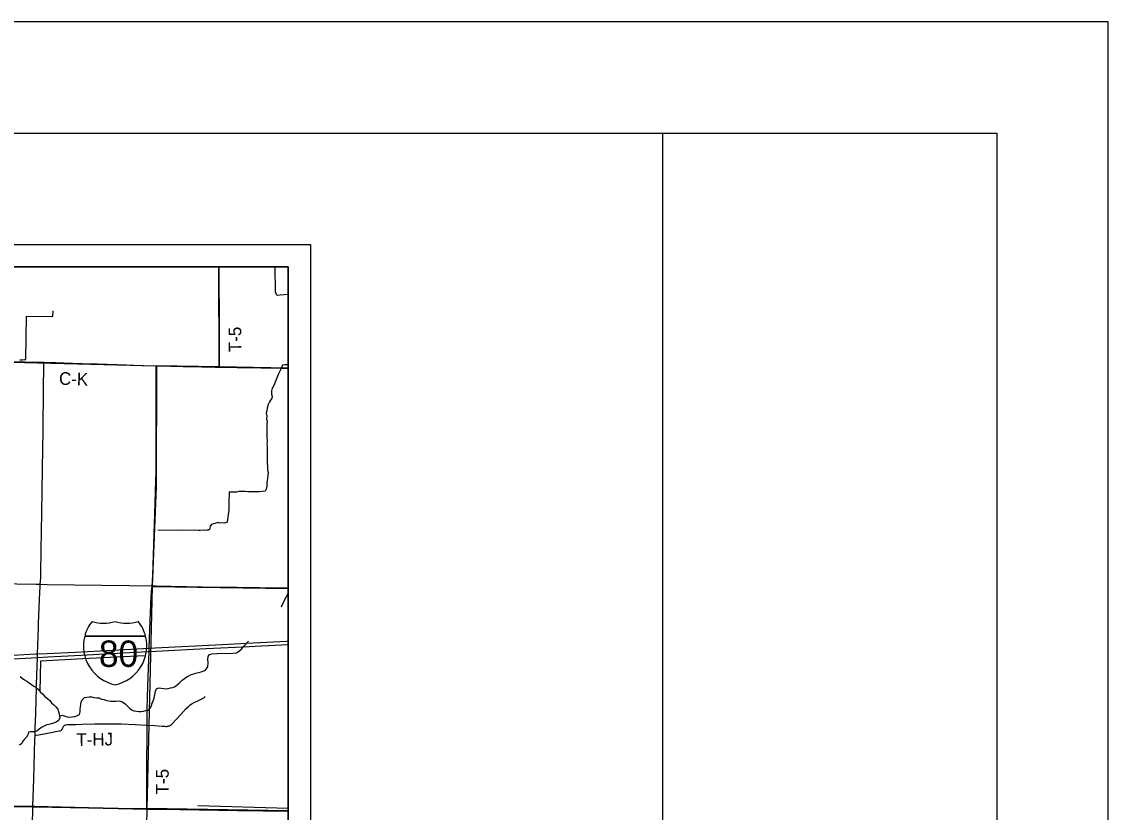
# Model space of a CAD drawing. Extents: x -21.7 to 34, y 0 to 22.
# Drawn here: x 29.12 to 34, y 18.453 to 22 of the extents above; entities that cross this region are included whole.
import ezdxf

# ---------------------------------------------------------------- set-up
doc = ezdxf.new("R2010")
doc.units = 0
for name, color, linetype in [('Default', 7, 'Continuous'), ('GM_X_County_Road', 7, 'Continuous'), ('GM_X_County_Road_Text', 7, 'Continuous'), ('GM_X_Interchange_Ramps', 7, 'Continuous'), ('GM_X_Interstate_Location', 7, 'Continuous'), ('GM_X_Interstate_Route', 7, 'Continuous'), ('GM_X_Interstate_Shield', 7, 'Continuous'), ('GM_X_Minor_River', 7, 'Continuous'), ('GM_X_Township_Road', 7, 'Continuous'), ('GM_X_Township_Road_Text', 7, 'Continuous'), ('SH_Border', 7, 'Continuous'), ('SH_Cut_Line', 7, 'Continuous'), ('SH_Data', 7, 'Continuous')]:
    doc.layers.add(name, color=color, linetype=linetype)

msp = doc.modelspace()

# ---------------------------------------------------------------- linework, layer by layer
at = {"layer": 'Default'}
for points in [[(30.006, 20.9), (29.0167, 20.9), (29.0129, 20.4744), (29.7259, 20.4559), (30.0077, 20.4514)], [(30.3167, 20.4464), (30.3167, 20.9), (30.006, 20.9), (30.0077, 20.4514)], [(30.3167, 19.4571), (30.3167, 20.4464), (30.0077, 20.4514), (29.7259, 20.4559), (29.7237, 19.914), (29.706, 19.4656)], [(30.3167, 18.4589), (30.3167, 19.4571), (29.706, 19.4656), (29.6819, 18.4704)], [(30.3167, 17.4474), (30.3167, 18.4589), (29.6819, 18.4704), (29.6632, 17.4593)]]:
    msp.add_lwpolyline(points, close=True, dxfattribs=at)
at = {"layer": 'GM_X_County_Road'}
for points in [[(29.0187, 20.4775), (29.0655, 20.4763), (29.2054, 20.4724), (29.2205, 20.472)], [(29.2037, 19.4762), (29.2057, 19.5049), (29.2066, 19.5267), (29.2084, 19.6294), (29.2108, 19.7973), (29.2122, 19.8938), (29.2152, 20.0866), (29.2164, 20.1581), (29.2164, 20.1706), (29.2166, 20.2017), (29.2173, 20.2421), (29.2179, 20.2763), (29.2186, 20.3447), (29.2203, 20.4629), (29.2205, 20.472)], [(29.2205, 20.472), (29.2738, 20.4705), (29.3483, 20.4681), (29.3918, 20.4667), (29.4602, 20.4648), (29.5908, 20.4605), (29.6591, 20.4581), (29.7244, 20.4565)], [(29.7244, 20.4565), (29.7897, 20.4549), (29.8456, 20.4539), (29.8736, 20.4531), (29.9296, 20.4519), (29.9886, 20.4505), (30.0091, 20.4503)], [(30.0091, 20.4503), (30.0881, 20.4492), (30.1938, 20.4479), (30.2902, 20.4464), (30.3167, 20.4461)], [(28.5268, 19.4873), (28.5787, 19.4865), (28.7466, 19.4836), (28.8305, 19.4824), (28.874, 19.4815), (28.9611, 19.4803), (29.0108, 19.4795), (29.1849, 19.4765), (29.2037, 19.4762)], [(29.1805, 18.7981), (29.1813, 18.8288), (29.183, 18.8628), (29.1837, 18.8942), (29.1842, 18.9147), (29.1848, 18.9395), (29.1875, 19.0266), (29.191, 19.148), (29.1911, 19.1508), (29.1915, 19.1634), (29.1953, 19.2813), (29.1963, 19.2999), (29.1996, 19.4088), (29.2011, 19.4398), (29.2029, 19.4646), (29.2037, 19.4762)], [(29.2037, 19.4762), (29.2345, 19.4757), (29.3557, 19.4738), (29.6044, 19.4699), (29.7055, 19.4687)], [(29.7055, 19.4687), (29.7225, 19.4685), (29.9992, 19.4638), (30.0396, 19.4631), (30.0862, 19.4625), (30.1888, 19.4609), (30.2572, 19.4601), (30.3167, 19.4599)], [(29.1704, 18.4779), (29.1705, 18.4805), (29.1742, 18.6015), (29.1797, 18.7815), (29.1805, 18.7981)], [(28.1596, 18.4872), (28.2546, 18.4861), (28.5561, 18.4831), (28.6742, 18.4819), (28.8328, 18.4806), (29.0193, 18.4793), (29.1704, 18.4779)], [(29.1578, 17.5101), (29.1581, 17.535), (29.1585, 17.5645), (29.1595, 17.6359), (29.1616, 17.7788), (29.1626, 17.8564), (29.1637, 17.9433), (29.1649, 18.0241), (29.1659, 18.1172), (29.166, 18.1358), (29.1666, 18.1824), (29.167, 18.229), (29.168, 18.3035), (29.1704, 18.4779)], [(29.1704, 18.4779), (29.1778, 18.4778), (29.4202, 18.4727), (29.6191, 18.4685), (29.6815, 18.4674)], [(29.6815, 18.4674), (29.7434, 18.4663), (30.0916, 18.4614), (30.3167, 18.4584)]]:
    msp.add_lwpolyline(points, dxfattribs=at)
at = {"layer": 'GM_X_Interchange_Ramps'}
for points in [[(29.019, 18.4799), (29.1702, 18.4785), (29.1776, 18.4784), (29.42, 18.4733), (29.6189, 18.4691), (29.6813, 18.468), (29.7432, 18.4669), (30.0914, 18.462), (30.3167, 18.4589), (30.3167, 20.9), (27.8768, 20.9)], [(27.5987, 14.1), (30.3167, 14.1), (30.3167, 18.4589), (30.0914, 18.462), (29.7432, 18.4669), (29.6813, 18.468), (29.6189, 18.4691), (29.42, 18.4733), (29.1776, 18.4784), (29.1702, 18.4785), (29.019, 18.4799)]]:
    msp.add_lwpolyline(points, dxfattribs=at)
at = {"layer": 'GM_X_Interstate_Route'}
for points in [[(29.0829, 19.1422), (29.191, 19.148), (29.2382, 19.1505), (29.3872, 19.1585), (29.5207, 19.1651), (29.6883, 19.1739), (29.6924, 19.1741), (29.7223, 19.1754), (29.949, 19.1873), (30.1136, 19.1954), (30.1974, 19.1999), (30.3167, 19.2058)], [(29.0862, 19.1585), (29.1297, 19.1605), (29.1856, 19.1632), (29.1915, 19.1634), (29.2353, 19.1655), (29.3626, 19.1719), (29.639, 19.1862), (29.693, 19.1891), (29.7197, 19.1905), (30.0209, 19.2062), (30.1296, 19.2121), (30.3097, 19.2213), (30.3167, 19.2216)]]:
    msp.add_lwpolyline(points, dxfattribs=at)
at = {"layer": 'GM_X_Interstate_Shield'}
for p, q in [((29.4033, 19.2429), (29.6765, 19.2429)), ((29.6765, 19.2429), (29.4033, 19.2429)), ((29.6765, 19.2429), (29.4033, 19.2429))]:
    msp.add_line(p, q, dxfattribs=at)
for centre, start, end in [((29.5754, 19.1994), 141.669, 165.8066), ((29.488, 19.4793), 253.0091, 286.9909), ((29.5918, 19.4793), 253.0091, 286.9909), ((29.5044, 19.1994), 14.1934, 38.331), ((29.5754, 19.1994), 165.8066, 258.463), ((29.5044, 19.1994), 281.537, 14.1934)]:
    msp.add_arc(centre, 0.1776, start, end, dxfattribs=at)
at = {"layer": 'GM_X_Minor_River'}
msp.add_line((30.3167, 18.4705), (29.911, 18.4812), dxfattribs=at)
for points in [[(30.2571, 20.9), (30.2581, 20.7874), (30.2622, 20.7828), (30.2635, 20.7763), (30.2688, 20.7732), (30.2817, 20.7741), (30.3167, 20.777)], [(29.1396, 20.4842), (29.1417, 20.6786), (29.2595, 20.6781), (29.2615, 20.7031)], [(29.1119, 20.4829), (29.1229, 20.4838), (29.1324, 20.4843)], [(29.1324, 20.4843), (29.1396, 20.4842)], [(30.3167, 20.4611), (30.303, 20.4607), (30.2908, 20.4587), (30.2856, 20.4444), (30.28, 20.4316), (30.2741, 20.4203), (30.2522, 20.3676), (30.2444, 20.356), (30.2419, 20.3446), (30.242, 20.3287), (30.2455, 20.318), (30.2431, 20.3104), (30.238, 20.3018), (30.2326, 20.294), (30.227, 20.2831), (30.2225, 20.2661), (30.2212, 20.2547), (30.2187, 20.2437), (30.221, 20.23), (30.22, 20.2171), (30.2228, 20.2057), (30.2207, 20.1932), (30.2218, 20.1734), (30.2207, 20.156), (30.2217, 20.1491), (30.221, 20.1366), (30.2222, 20.1184), (30.2219, 20.1062), (30.2221, 20.0967), (30.2222, 20.0618), (30.2223, 20.0303), (30.2228, 20.0196), (30.2245, 20.0067), (30.2241, 19.9904), (30.2269, 19.9766), (30.2238, 19.9535), (30.221, 19.9289), (30.2211, 19.9164), (30.2178, 19.9028), (30.2131, 19.8934), (30.2002, 19.8925), (30.1876, 19.8905), (30.1354, 19.8904), (30.1259, 19.8917), (30.1104, 19.8928), (30.096, 19.8919), (30.0853, 19.8899), (30.0516, 19.889), (30.0506, 19.842), (30.0511, 19.8294), (30.0509, 19.818), (30.0503, 19.8082), (30.0424, 19.754), (30.0325, 19.7504), (30.0231, 19.7518), (30.0098, 19.7498), (30.0015, 19.7533), (29.9878, 19.7483), (29.9802, 19.7473), (29.9725, 19.7437), (29.9674, 19.7369), (29.965, 19.7283), (29.9634, 19.7218), (29.9599, 19.7189), (29.9538, 19.7182), (29.9462, 19.718), (29.9356, 19.7182), (29.922, 19.7174), (29.914, 19.7179), (29.8978, 19.719), (29.8326, 19.7176), (29.7322, 19.7189)], [(29.9577, 19.1243), (29.9569, 19.1395), (29.9571, 19.152), (29.9641, 19.1614), (29.9748, 19.1642), (29.9979, 19.1652), (30.0684, 19.1665), (30.0847, 19.1681), (30.094, 19.1739), (30.1067, 19.1851), (30.1183, 19.1989), (30.1386, 19.2207)], [(29.2027, 18.9937), (29.2058, 19.1326), (29.3951, 19.1428), (29.6697, 19.1559)], [(29.2906, 18.8845), (29.3039, 18.888), (29.3141, 18.8836), (29.3246, 18.8811), (29.3352, 18.8794), (29.3466, 18.8811), (29.3588, 18.8827), (29.371, 18.8866), (29.3806, 18.8921), (29.3823, 18.9039), (29.3825, 18.9149), (29.3839, 18.9259), (29.3856, 18.9372), (29.3877, 18.9471), (29.3921, 18.958), (29.4022, 18.9684), (29.4128, 18.9697), (29.4238, 18.971), (29.4348, 18.9704), (29.445, 18.9687), (29.4582, 18.9665), (29.4681, 18.9663), (29.4793, 18.9612), (29.4906, 18.959), (29.5011, 18.9539), (29.5114, 18.9537), (29.5212, 18.9516), (29.5318, 18.9514), (29.5428, 18.9519), (29.5534, 18.9528), (29.564, 18.9511), (29.5749, 18.9475), (29.585, 18.94), (29.595, 18.9296), (29.6047, 18.9207), (29.6144, 18.9133), (29.6245, 18.9081), (29.6456, 18.9054), (29.6574, 18.9059), (29.668, 18.9069), (29.6775, 18.9093), (29.689, 18.9118), (29.6983, 18.9214), (29.7038, 18.9323), (29.7066, 18.9425), (29.711, 18.9531), (29.7147, 18.9644), (29.7172, 18.9761), (29.72, 18.9867), (29.7217, 18.9965), (29.7254, 19.0063), (29.7357, 19.0107), (29.7463, 19.0101), (29.758, 19.0079), (29.7686, 19.0074), (29.7781, 19.0087), (29.788, 19.0108), (29.7986, 19.0136), (29.8089, 19.0179), (29.8201, 19.0264), (29.8309, 19.0353), (29.8413, 19.0458), (29.8509, 19.0532), (29.8613, 19.0602), (29.8716, 19.0653), (29.882, 19.0711), (29.8927, 19.074), (29.9022, 19.0772), (29.9144, 19.0804), (29.9258, 19.0835), (29.9357, 19.0864), (29.9454, 19.0903), (29.956, 19.1058), (29.9577, 19.1243)], [(29.1127, 19.0623), (29.1225, 19.0553), (29.1333, 19.0479), (29.1438, 19.042), (29.1542, 19.0342), (29.1751, 19.0193), (29.1852, 19.0126), (29.1953, 19.0033), (29.2027, 18.9937), (29.2146, 18.9824), (29.2246, 18.9731), (29.2365, 18.9634), (29.2462, 18.9541), (29.2539, 18.9444), (29.2644, 18.9355), (29.2729, 18.9254), (29.2825, 18.915), (29.2861, 18.9051), (29.2882, 18.8948), (29.2906, 18.8845), (29.2919, 18.8746), (29.286, 18.8644), (29.2749, 18.8571), (29.2631, 18.8527), (29.2535, 18.8495), (29.2429, 18.8475), (29.233, 18.8454), (29.2215, 18.8388), (29.2096, 18.8329), (29.1993, 18.8263), (29.1896, 18.8178), (29.1793, 18.8142), (29.1695, 18.8136), (29.1596, 18.8146), (29.1501, 18.8125), (29.1476, 18.8011), (29.1421, 18.7906), (29.1325, 18.7817), (29.1258, 18.772), (29.1211, 18.7618), (29.1107, 18.7548)]]:
    msp.add_lwpolyline(points, dxfattribs=at)
at = {"layer": 'GM_X_Township_Road'}
for points in [[(30.0091, 20.4503), (30.0091, 20.4567), (30.0092, 20.4722), (30.0089, 20.5374), (30.0082, 20.6151), (30.0065, 20.9)], [(29.7055, 19.4687), (29.7074, 19.4904), (29.7088, 19.5152), (29.7151, 19.7015), (29.7177, 19.7915), (29.7227, 19.9405), (29.7235, 19.9778), (29.7237, 20.0461), (29.7239, 20.2015), (29.7241, 20.2978), (29.7244, 20.4469), (29.7244, 20.4565)], [(29.7244, 20.4565), (29.7897, 20.4549), (29.8456, 20.4539), (29.8736, 20.4531), (29.9296, 20.4519), (29.9886, 20.4505), (30.0091, 20.4503)], [(28.5268, 19.4873), (28.5787, 19.4865), (28.7466, 19.4836), (28.8305, 19.4824), (28.874, 19.4815), (28.9611, 19.4803), (29.0108, 19.4795), (29.1849, 19.4765), (29.2037, 19.4762)], [(29.2037, 19.4762), (29.2345, 19.4757), (29.3557, 19.4738), (29.6044, 19.4699), (29.7055, 19.4687)], [(29.6842, 18.8442), (29.6844, 18.9193), (29.685, 18.966), (29.6866, 19.0188), (29.6896, 19.0995), (29.6924, 19.1741), (29.693, 19.1891), (29.6977, 19.3136), (29.7019, 19.4191), (29.7034, 19.444), (29.7055, 19.4687)], [(29.7055, 19.4687), (29.7225, 19.4685), (29.9992, 19.4638), (30.0396, 19.4631), (30.0862, 19.4625), (30.1888, 19.4609), (30.2572, 19.4601), (30.3167, 19.4599)], [(30.2867, 19.3752), (30.2996, 19.402), (30.3167, 19.4352)], [(29.6842, 18.8442), (29.7164, 18.8429), (29.7505, 18.8401), (29.7629, 18.8388), (29.7691, 18.8385), (29.7723, 18.8386), (29.7754, 18.8389), (29.7784, 18.8394), (29.7814, 18.8402), (29.7843, 18.8413), (29.7871, 18.8427), (29.7897, 18.8444), (29.7921, 18.8463), (29.7967, 18.8506), (29.8137, 18.8687), (29.8347, 18.8918), (29.8579, 18.917), (29.8688, 18.9281), (29.8759, 18.9341), (29.8809, 18.9378), (29.8862, 18.9411), (29.8944, 18.9455), (29.9112, 18.9537), (29.9378, 18.9664), (29.9401, 18.9679), (29.9417, 18.9692), (29.9425, 18.9705), (29.9443, 18.9735)], [(29.1805, 18.7981), (29.1867, 18.7988), (29.2048, 18.8025), (29.26, 18.8125), (29.2721, 18.8149), (29.2905, 18.818), (29.2935, 18.8188), (29.2964, 18.82), (29.299, 18.8216), (29.3012, 18.8238), (29.3029, 18.8264), (29.3042, 18.8292), (29.3061, 18.8352), (29.3073, 18.8381), (29.309, 18.8406), (29.3113, 18.8428), (29.3139, 18.8444), (29.3168, 18.8454), (29.3199, 18.8461), (29.3261, 18.8466), (29.3633, 18.8474), (29.3912, 18.8481), (29.4471, 18.8503), (29.5, 18.8506), (29.5342, 18.8501), (29.5686, 18.8492), (29.6292, 18.8469), (29.679, 18.8444), (29.6842, 18.8442)], [(29.6815, 18.4674), (29.6816, 18.4752), (29.6819, 18.5001), (29.6825, 18.587), (29.683, 18.6802), (29.6836, 18.7889), (29.6841, 18.8324), (29.6842, 18.8442)]]:
    msp.add_lwpolyline(points, dxfattribs=at)
at = {"layer": 'SH_Border'}
msp.add_line((32, 0.5), (32, 21.5), dxfattribs=at)
msp.add_lwpolyline([(1.5, 21.5), (33.5, 21.5), (33.5, 0.5), (1.5, 0.5)], close=True, dxfattribs=at)
at = {"layer": 'SH_Cut_Line'}
msp.add_lwpolyline([(0, 0), (34, 0), (34, 22), (0, 22)], close=True, dxfattribs=at)
at = {"layer": 'SH_Data'}
for p, q in [((23.5167, 20.9), (30.3167, 20.9)), ((30.3167, 20.9), (30.3167, 14.1))]:
    msp.add_line(p, q, dxfattribs=at)
for points in [[(23.4167, 21), (30.4167, 21), (30.4167, 14), (23.4167, 14)], [(23.5167, 20.9), (30.3167, 20.9), (30.3167, 14.1), (23.5167, 14.1)]]:
    msp.add_lwpolyline(points, close=True, dxfattribs=at)

# ---------------------------------------------------------------- texts
at = {"layer": 'GM_X_County_Road_Text'}
msp.add_text('C-K', height=0.05682, rotation=358.0099, dxfattribs=at).set_placement((29.287, 20.3717))
at = {"layer": 'GM_X_Interstate_Location'}
msp.add_text('80', height=0.000189, rotation=0, dxfattribs=at).set_placement((29.5012, 19.1281))
for s in ['.', '-', ',']:
    msp.add_text(s, height=0.000189, dxfattribs=at).set_placement((29.5399, 19.1673))
at = {"layer": 'GM_X_Interstate_Shield'}
msp.add_text('80', height=0.11837, dxfattribs=at).set_placement((29.4672, 19.1053))
at = {"layer": 'GM_X_Township_Road_Text'}
for s, rotation, p in [('T-5', 90.4772, (30.1072, 20.5178)), ('T-HJ', 0.9903, (29.3664, 18.7502)), ('T-5', 90, (29.7805, 18.5337))]:
    msp.add_text(s, height=0.05682, rotation=rotation, dxfattribs=at).set_placement(p)

doc.saveas('drawing.dxf')
